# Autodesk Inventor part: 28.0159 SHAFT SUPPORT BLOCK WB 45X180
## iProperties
Created: 2007-06
Part Number: 28.0159 SHAFT SUPPORT BLOCK WB 45X180
Material: Aluminum-6061
Document SubType Name: Modeling
Designer: Andy Moles
Density: 1 g/cm^3
Author: Andy Moles
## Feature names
1. Extrusion1
2. Extrusion2
3. Extrusion3
